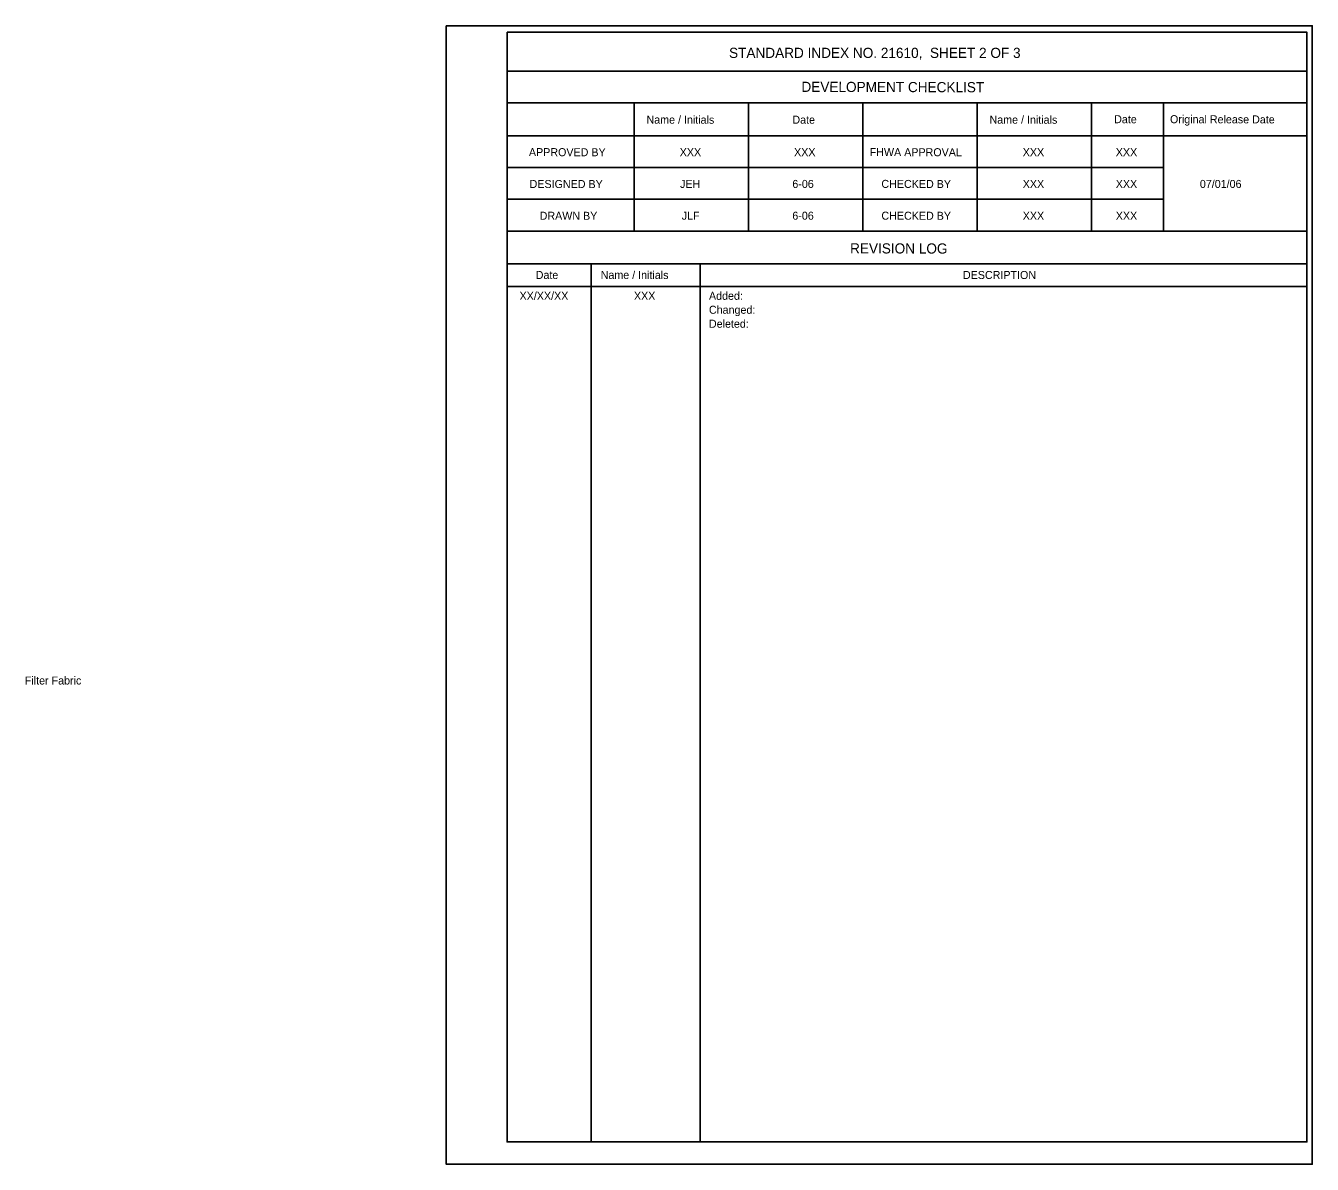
# Model space of a CAD drawing. Extents: x 10624 to 10731, y 76456 to 76513.
# Drawn here: x 10682.29 to 10730.9, y 76465.91 to 76508.91 of the extents above; entities that cross this region are included whole.
import ezdxf

# ---------------------------------------------------------------- set-up
doc = ezdxf.new("R2010")
doc.units = 0
for name, color, linetype in [('Border', 7, 'Continuous'), ('PlotBorder_dp', 7, 'Continuous'), ('TextStructures', 7, 'Continuous')]:
    doc.layers.add(name, color=color, linetype=linetype)

msp = doc.modelspace()

# ---------------------------------------------------------------- linework, layer by layer
at = {"layer": 'Border'}
for p, q in [((10730.698, 76507.194), (10700.478, 76507.194)), ((10730.698, 76505.994), (10700.478, 76505.994)), ((10705.278, 76505.994), (10705.278, 76501.153)), ((10709.598, 76505.994), (10709.598, 76501.153)), ((10713.918, 76505.994), (10713.918, 76501.153)), ((10718.238, 76505.994), (10718.238, 76501.153)), ((10722.558, 76505.994), (10722.558, 76501.153)), ((10725.28, 76505.994), (10725.28, 76501.153)), ((10730.698, 76504.753), (10700.478, 76504.753)), ((10725.28, 76503.553), (10700.478, 76503.553)), ((10725.28, 76502.353), (10700.478, 76502.353)), ((10730.698, 76501.153), (10700.478, 76501.153)), ((10730.698, 76499.911), (10700.478, 76499.911)), ((10703.658, 76499.911), (10703.658, 76466.751)), ((10707.772, 76499.911), (10707.772, 76466.751)), ((10730.698, 76499.065), (10700.478, 76499.065))]:
    msp.add_line(p, q, dxfattribs=at)
msp.add_lwpolyline([(10700.478, 76508.665), (10730.698, 76508.665), (10730.698, 76466.751), (10700.478, 76466.751)], close=True, dxfattribs=at)
at = {"layer": 'PlotBorder_dp'}
msp.add_line((10698.182, 76465.909), (10698.182, 76465.909), dxfattribs=at)
msp.add_lwpolyline([(10698.182, 76508.909), (10730.902, 76508.909), (10730.902, 76465.909), (10698.182, 76465.909)], close=True, dxfattribs=at)

# ---------------------------------------------------------------- texts
at = {"layer": 'TextStructures'}
for s, height, p in [('STANDARD INDEX NO. 21610,  SHEET 2 OF 3', 0.384, (10708.867, 76507.693)), ('XXX', 0.3024, (10707.003, 76503.983)), ('XXX', 0.3024, (10711.323, 76503.983)), ('XXX', 0.3024, (10719.963, 76503.983)), ('XXX', 0.3024, (10723.478, 76503.983)), ('JEH', 0.3024, (10707.014, 76502.783)), ('6-06', 0.3024, (10711.258, 76502.783)), ('XXX', 0.3024, (10719.963, 76502.783)), ('XXX', 0.3024, (10723.478, 76502.783)), ('07/01/06', 0.3024, (10726.655, 76502.783)), ('JLF', 0.3024, (10707.077, 76501.583)), ('6-06', 0.3024, (10711.258, 76501.583)), ('XXX', 0.3024, (10719.963, 76501.583)), ('XXX', 0.3024, (10723.478, 76501.583)), ('DESCRIPTION', 0.3024, (10717.703, 76499.345)), ('XX/XX/XX', 0.3024, (10700.951, 76498.558)), ('XXX', 0.3024, (10705.273, 76498.558)), ('Added:', 0.3024, (10708.107, 76498.558)), ('Changed:', 0.3024, (10708.107, 76498.031)), ('Deleted:', 0.3024, (10708.107, 76497.503)), ('Filter Fabric', 0.3024, (10682.26, 76484.028))]:
    msp.add_text(s, height=height, dxfattribs=at).set_placement(p)
for s, height, p in [('DEVELOPMENT CHECKLIST', 0.384, (10711.601, 76506.41)), ('Name / Initials', 0.3024, (10705.747, 76505.213)), ('Date', 0.3024, (10711.259, 76505.21)), ('Name / Initials', 0.3024, (10718.707, 76505.213)), ('Date', 0.3024, (10723.416, 76505.228)), ('Original Release Date', 0.3024, (10725.526, 76505.228)), ('APPROVED BY', 0.3024, (10701.305, 76503.985)), ('FHWA APPROVAL', 0.3024, (10714.18, 76503.986)), ('DESIGNED BY', 0.3024, (10701.331, 76502.783)), ('CHECKED BY', 0.3024, (10714.623, 76502.785)), ('DRAWN BY', 0.3024, (10701.71, 76501.583)), ('CHECKED BY', 0.3024, (10714.623, 76501.585)), ('REVISION LOG', 0.384, (10713.439, 76500.311)), ('Date', 0.3024, (10701.561, 76499.346)), ('Name / Initials', 0.3024, (10704.016, 76499.349))]:
    msp.add_text(s, height=height, rotation=359.8756, dxfattribs=at).set_placement(p)

doc.saveas('drawing.dxf')
